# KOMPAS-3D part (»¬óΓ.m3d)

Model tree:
1. Эскиз:1
2. Операция выдавливания:1
     Расстояние 1 = 3.7; Расстояние 2 = 3.7
3. Эскиз:2
4. Вырезать элемент выдавливания:1
     Расстояние 1 = 1
5. Эскиз:3
6. Вырезать элемент выдавливания:2
     Расстояние 1 = 1
7. Эскиз:4
8. Вырезать элемент выдавливания:3
     Расстояние 1 = 2
9. Эскиз:5
10. Операция выдавливания:2
     Расстояние 1 = 2; Расстояние 2 = 3.7
11. Эскиз:6
12. Вырезать элемент выдавливания:4
     Расстояние 1 = 2
13. Эскиз:7
14. Вырезать элемент выдавливания:5
     Расстояние 1 = 32
15. Эскиз:8
16. Вырезать элемент выдавливания:6
     Расстояние 2 = 2; Расстояние 1 = 3
17. Эскиз:9
18. Операция выдавливания:3
     Расстояние 1 = 0.2; Расстояние 2 = 4.5
19. Эскиз:10
20. Вырезать элемент выдавливания:7
     Расстояние 2 = 2; Расстояние 1 = 0.3
21. Эскиз:11
22. Операция выдавливания:4
     Расстояние 1 = 0.3; Расстояние 2 = 4.5
23. Скругление:2
     Радиус = 0.5
24. Скругление:3
     Радиус = 0.1
25. Скругление:4
     Радиус = 0.2
26. Скругление:5
     Радиус = 0.2
27. Скругление:6
     Радиус = 0.2
28. Скругление:7
     Радиус = 0.2
29. Скругление:8
     Радиус = 0.2
30. Скругление:9
     Радиус = 0.2
31. Скругление:10
     Радиус = 0.2
32. Эскиз:12
33. Операция выдавливания:5
     Расстояние 1 = 0.2; Расстояние 2 = 4.5
34. Скругление:11
     Радиус = 0.2
35. Скругление:12
     Радиус = 0.2
36. Эскиз:13
37. Вырезать элемент выдавливания:8
     Расстояние 2 = 2; Расстояние 1 = 1
38. Скругление:13
     Радиус = 0.2
39. Скругление:14
     Радиус = 0.2
40. Скругление:15
     Радиус = 0.2
41. Скругление:16
     Радиус = 0.2
42. Эскиз:14
43. Операция выдавливания:6
     Расстояние 1 = 56.9; Угол 1 = 0.2; Расстояние 2 = 4.5
44. Эскиз:15
45. Операция выдавливания:7
     Расстояние 1 = 3; Расстояние 2 = 4.5
46. Эскиз:16
47. Операция выдавливания:8
     Расстояние 1 = 2; Угол 1 = 3; Расстояние 2 = 4.5
48. Эскиз:17
49. Операция выдавливания:9
     Расстояние 1 = 12.6; Расстояние 2 = 4.5
50. Эскиз:18
51. Операция выдавливания:10
     Расстояние 1 = 1; Расстояние 2 = 4.5
52. Скругление:17
     Радиус = 0.2
53. Скругление:18
     Радиус = 0.2
54. Скругление:19
     Радиус = 0.2
55. Эскиз:19
56. Операция выдавливания:11
     Расстояние 1 = 2.2; Расстояние 2 = 4.5
57. Скругление:20
     Радиус = 0.1
58. Скругление:21
     Радиус = 0.05
59. Смещенная плоскость:1
     Расстояние = 25
60. Эскиз:20
61. Операция выдавливания:12
     Расстояние 1 = 1; Расстояние 2 = 4.5
62. Скругление:22
     Радиус = 0.05
63. Смещенная плоскость:2
     Расстояние = 1
64. Эскиз:21
65. Операция выдавливания:13
     Расстояние 1 = 0.2; Расстояние 2 = 4.5
66. Скругление:23
     Радиус = 0.05
67. Эскиз:22
68. Операция выдавливания:14
     Расстояние 1 = 0.2; Расстояние 2 = 0.2
69. Эскиз:23
70. Операция выдавливания:15
     Расстояние 1 = 0.3; Расстояние 2 = 0.3
71. Скругление:24
     Радиус = 0.05
72. Эскиз:24
73. Вырезать элемент выдавливания:9
     Расстояние 2 = 2; Расстояние 1 = 1
74. Смещенная плоскость:3
     Расстояние = 18.1
75. Смещенная плоскость:4
     Расстояние = 10.8
76. Смещенная плоскость:5
     Расстояние = 2.7
77. Эскиз:25
78. Операция выдавливания:16
     Расстояние 1 = 1.3; Расстояние 2 = 0.3
79. Эскиз:26
80. Операция выдавливания:17
     Расстояние 1 = 0.5; Угол 1 = 13; Расстояние 2 = 0.3
81. Эскиз:27
82. Операция выдавливания:18
     Расстояние 1 = 2; Расстояние 2 = 0.3
83. Эскиз:28
84. Операция выдавливания:19
     Расстояние 1 = 0.5; Угол 1 = 20; Расстояние 2 = 0.3
85. Эскиз:29
86. Операция выдавливания:20
     Расстояние 1 = 5.5; Угол 1 = 5; Расстояние 2 = 0.3
87. Эскиз:30
88. Вырезать элемент выдавливания:10
     Расстояние 2 = 2; Расстояние 1 = 51
89. Эскиз:31
90. Операция выдавливания:21
     Расстояние 1 = 0.5; Расстояние 2 = 6
91. Эскиз:32
92. Вырезать элемент выдавливания:11
     Расстояние 2 = 2; Расстояние 1 = 39.276
93. Эскиз:33
94. Вырезать элемент выдавливания:12
     Расстояние 2 = 2; Расстояние 1 = 1
95. Скругление:25
     Радиус = 0.5
96. Скругление:26
     Радиус = 0.3
97. Скругление:27
     Радиус = 0.3
98. Эскиз:34
99. Операция выдавливания:22
     Расстояние 1 = 2; Расстояние 2 = 1
100. Скругление:28
     Радиус = 0.3
101. Скругление:29
     Радиус = 0.3
102. Эскиз:35
103. Вырезать элемент выдавливания:13
     Расстояние 2 = 2; Расстояние 1 = 1
104. Эскиз:36
105. Операция выдавливания:23
     Расстояние 1 = 3; Расстояние 2 = 1
106. Скругление:30
     Радиус = 1
107. Эскиз:37
108. Вырезать элемент выдавливания:14
     Расстояние 2 = 2; Расстояние 1 = 1
109. Эскиз:38
110. Вырезать элемент выдавливания:15
     Расстояние 2 = 2; Расстояние 1 = 7.76109
111. Эскиз:39
112. Операция выдавливания:24
     Расстояние 1 = 3.2; Расстояние 2 = 1
113. Скругление:33
     Радиус = 0.5
114. Эскиз:40
115. Операция выдавливания:25
     Расстояние 1 = 3.2; Расстояние 2 = 1
116. Скругление:34
     Радиус = 0.5
117. Скругление:35
     Радиус = 0.5

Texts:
  Сплав АЛ8  ГОСТ 1583-93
